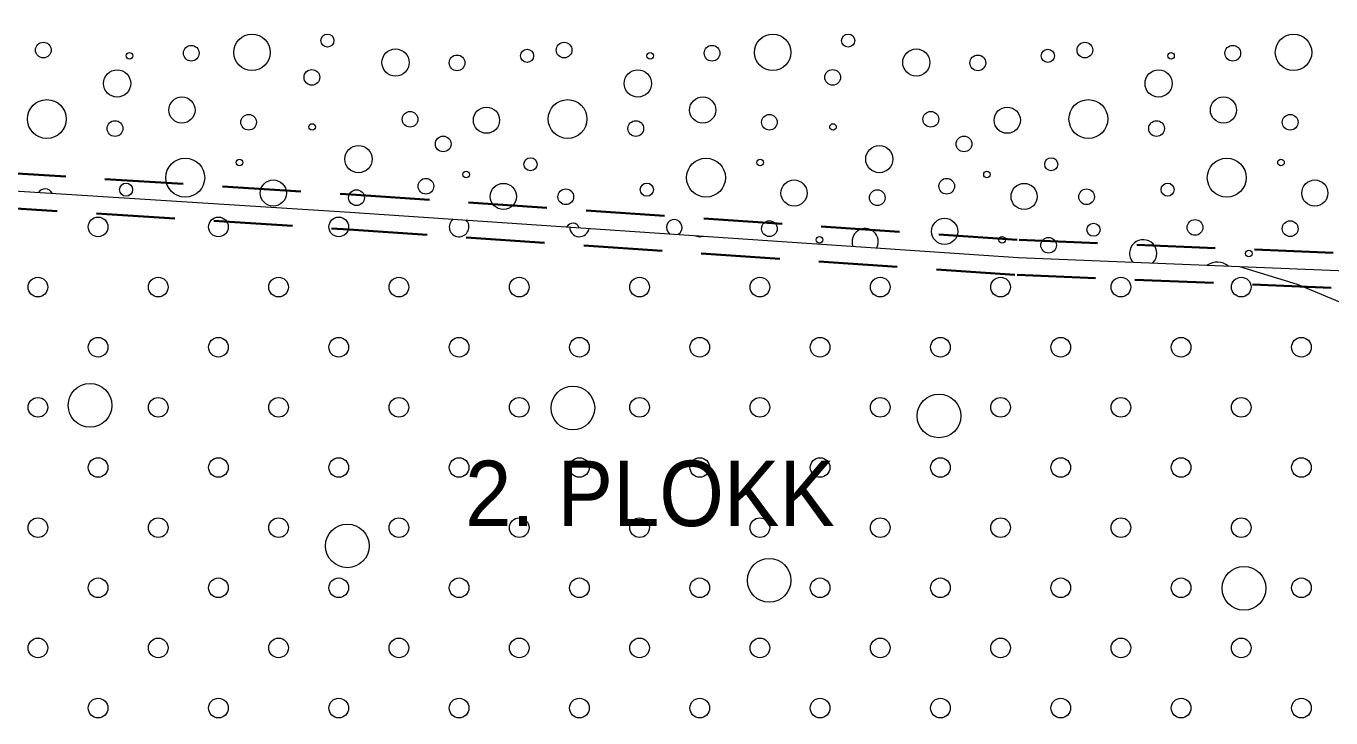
# Model space of a CAD drawing. Extents: x 640104 to 640970, y 6442278 to 6442689.
# Drawn here: x 640313.3 to 640373.1, y 6442364.5 to 6442396.3 of the extents above; entities that cross this region are included whole.
import ezdxf
from ezdxf.enums import TextEntityAlignment as Align

# ---------------------------------------------------------------- set-up
doc = ezdxf.new("R2010")
doc.units = 0
doc.header["$LTSCALE"] = 1.2
doc.linetypes.add('MEDIUM_DASHED', pattern=[4.5, 3, -1.5])
for name, color, linetype, lineweight in [('31', 7, 'Continuous', 13), ('35', 7, 'Continuous', 35), ('41', 7, 'Continuous', 13), ('42', 7, 'Continuous', 13), ('47', 7, 'Continuous', 13)]:
    doc.layers.add(name, color=color, linetype=linetype, lineweight=lineweight)

msp = doc.modelspace()

# ---------------------------------------------------------------- linework, layer by layer
at = {"layer": '31'}
for points in [[(640139.08, 6442423.82), (640151.96, 6442423.75), (640173.66, 6442421.26), (640213.16, 6442416.61), (640233.94, 6442414.53), (640242.79, 6442413.66), (640295.17, 6442389.83), (640328.15, 6442387.74), (640358.78, 6442385.66), (640377.96, 6442384.87), (640391.41, 6442383.72), (640397.31, 6442383.01), (640414.42, 6442381.45)], [(640368.92, 6442385.24), (640371.57, 6442384.43), (640374.23, 6442383.31), (640378.94, 6442380.49), (640385.79, 6442376.51), (640388.32, 6442375.25), (640390.29, 6442374.75), (640393.64, 6442373.85), (640400.93, 6442372.38), (640406.33, 6442371.82), (640411.39, 6442371.54), (640414.6, 6442371.41), (640423.41, 6442371.54), (640447.85, 6442370.88), (640460.41, 6442370.88), (640471.22, 6442370.34), (640473.77, 6442369.96)]]:
    msp.add_lwpolyline(points, dxfattribs=at)
at = {"layer": '35', "linetype": 'MEDIUM_DASHED'}
for points in [[(640153.52, 6442424.38), (640173.75, 6442422.06), (640213.24, 6442417.41), (640234.02, 6442415.33), (640243, 6442414.44), (640295.36, 6442390.62), (640328.2, 6442388.54), (640358.82, 6442386.46), (640378.01, 6442385.67), (640391.49, 6442384.52), (640397.4, 6442383.81), (640411.83, 6442382.49)], [(640153.52, 6442422.77), (640173.56, 6442420.47), (640213.07, 6442415.82), (640233.86, 6442413.74), (640242.58, 6442412.88), (640294.97, 6442389.04), (640328.09, 6442386.94), (640358.73, 6442384.86), (640377.91, 6442384.07), (640391.32, 6442382.92), (640397.23, 6442382.22), (640405.71, 6442381.44)]]:
    msp.add_lwpolyline(points, dxfattribs=at)
at = {"layer": '41'}
for centre, radius in [((640323.658, 6442395.062), 0.834), ((640327.116, 6442395.6), 0.3), ((640347.527, 6442395.062), 0.834), ((640350.985, 6442395.6), 0.3), ((640371.396, 6442395.062), 0.834), ((640314.095, 6442395.166), 0.36), ((640318.044, 6442394.901), 0.15), ((640320.875, 6442395.023), 0.36), ((640330.238, 6442394.594), 0.624), ((640336.266, 6442394.901), 0.3), ((640337.964, 6442395.166), 0.36), ((640341.913, 6442394.901), 0.15), ((640344.744, 6442395.023), 0.36), ((640354.107, 6442394.594), 0.624), ((640360.135, 6442394.901), 0.3), ((640361.833, 6442395.166), 0.36), ((640365.782, 6442394.901), 0.15), ((640368.613, 6442395.023), 0.36), ((640333.057, 6442394.579), 0.36), ((640356.926, 6442394.579), 0.36), ((640317.475, 6442393.637), 0.624), ((640326.403, 6442393.914), 0.36), ((640341.344, 6442393.637), 0.624), ((640350.272, 6442393.914), 0.36), ((640365.213, 6442393.637), 0.624), ((640314.255, 6442392.005), 0.889), ((640320.447, 6442392.417), 0.6), ((640338.124, 6442392.005), 0.889), ((640344.316, 6442392.417), 0.6), ((640361.993, 6442392.005), 0.889), ((640368.185, 6442392.417), 0.6), ((640323.504, 6442391.856), 0.36), ((640330.904, 6442391.993), 0.36), ((640334.406, 6442391.949), 0.6), ((640347.373, 6442391.856), 0.36), ((640354.773, 6442391.993), 0.36), ((640358.275, 6442391.949), 0.6), ((640371.242, 6442391.856), 0.36), ((640317.38, 6442391.569), 0.36), ((640326.42, 6442391.64), 0.15), ((640341.249, 6442391.569), 0.36), ((640350.289, 6442391.64), 0.15), ((640365.118, 6442391.569), 0.36), ((640328.542, 6442390.169), 0.624), ((640332.423, 6442390.861), 0.36), ((640352.411, 6442390.169), 0.624), ((640356.292, 6442390.861), 0.36), ((640320.598, 6442389.315), 0.893), ((640336.422, 6442389.93), 0.3), ((640344.467, 6442389.315), 0.893), ((640360.291, 6442389.93), 0.3), ((640368.336, 6442389.315), 0.893), ((640323.084, 6442390.008), 0.15), ((640333.476, 6442389.465), 0.15), ((640346.953, 6442390.008), 0.15), ((640357.345, 6442389.465), 0.15), ((640370.822, 6442390.008), 0.15), ((640317.888, 6442388.766), 0.3), ((640324.635, 6442388.61), 0.6), ((640331.631, 6442388.924), 0.36), ((640335.18, 6442388.454), 0.6), ((640341.757, 6442388.766), 0.3), ((640348.504, 6442388.61), 0.6), ((640355.5, 6442388.924), 0.36), ((640359.049, 6442388.454), 0.6), ((640365.626, 6442388.766), 0.3), ((640372.373, 6442388.61), 0.6), ((640328.449, 6442388.398), 0.36), ((640338.042, 6442388.44), 0.36), ((640352.318, 6442388.398), 0.36), ((640361.911, 6442388.44), 0.36), ((640347.373, 6442386.977), 0.36), ((640355.404, 6442386.854), 0.6), ((640362.229, 6442386.929), 0.3), ((640366.881, 6442387.034), 0.36), ((640371.242, 6442386.977), 0.36), ((640349.668, 6442386.464), 0.15), ((640358.041, 6442386.464), 0.15), ((640360.17, 6442386.217), 0.36), ((640369.349, 6442385.843), 0.15)]:
    msp.add_circle(centre, radius, dxfattribs=at)
for centre, radius, start, end in [((640314.173, 6442388.44), 0.36, 27.17527, 145.58427), ((640338.36, 6442386.929), 0.3, 19.35786, 152.87247), ((640343.012, 6442387.034), 0.36, 299.20248, 233.02785), ((640351.762, 6442386.386), 0.6, 331.71524, 200.51508), ((640364.505, 6442385.848), 0.624, 315.02616, 220.25663), ((640367.897, 6442384.605), 0.835, 52.08446, 123.19833)]:
    msp.add_arc(centre, radius, start, end, dxfattribs=at)
at = {"layer": '42'}
for centre in [(640316.604, 6442387.058), (640322.119, 6442387.058), (640327.635, 6442387.058), (640313.846, 6442384.3), (640319.362, 6442384.3), (640324.877, 6442384.3), (640330.392, 6442384.3), (640335.908, 6442384.3), (640341.423, 6442384.3), (640346.939, 6442384.3), (640352.454, 6442384.3), (640357.97, 6442384.3), (640363.485, 6442384.3), (640369, 6442384.3), (640316.604, 6442381.542), (640322.119, 6442381.542), (640327.635, 6442381.542), (640333.15, 6442381.542), (640338.666, 6442381.542), (640344.181, 6442381.542), (640349.696, 6442381.542), (640355.212, 6442381.542), (640360.727, 6442381.542), (640366.243, 6442381.542), (640371.758, 6442381.542), (640313.846, 6442378.785), (640319.362, 6442378.785), (640324.877, 6442378.785), (640330.392, 6442378.785), (640335.908, 6442378.785), (640341.423, 6442378.785), (640346.939, 6442378.785), (640352.454, 6442378.785), (640357.97, 6442378.785), (640363.485, 6442378.785), (640369, 6442378.785), (640316.604, 6442376.027), (640322.119, 6442376.027), (640327.635, 6442376.027), (640333.15, 6442376.027), (640338.666, 6442376.027), (640344.181, 6442376.027), (640349.696, 6442376.027), (640355.212, 6442376.027), (640360.727, 6442376.027), (640366.243, 6442376.027), (640371.758, 6442376.027), (640313.846, 6442373.269), (640319.362, 6442373.269), (640324.877, 6442373.269), (640330.392, 6442373.269), (640335.908, 6442373.269), (640341.423, 6442373.269), (640346.939, 6442373.269), (640352.454, 6442373.269), (640357.97, 6442373.269), (640363.485, 6442373.269), (640369, 6442373.269), (640316.604, 6442370.511), (640322.119, 6442370.511), (640327.635, 6442370.511), (640333.15, 6442370.511), (640338.666, 6442370.511), (640344.181, 6442370.511), (640349.696, 6442370.511), (640355.212, 6442370.511), (640360.727, 6442370.511), (640366.243, 6442370.511), (640371.758, 6442370.511), (640313.846, 6442367.754), (640319.362, 6442367.754), (640324.877, 6442367.754), (640330.392, 6442367.754), (640335.908, 6442367.754), (640341.423, 6442367.754), (640346.939, 6442367.754), (640352.454, 6442367.754), (640357.97, 6442367.754), (640363.485, 6442367.754), (640369, 6442367.754), (640316.604, 6442364.996), (640322.119, 6442364.996), (640327.635, 6442364.996), (640333.15, 6442364.996), (640338.666, 6442364.996), (640344.181, 6442364.996), (640349.696, 6442364.996), (640355.212, 6442364.996), (640360.727, 6442364.996), (640366.243, 6442364.996), (640371.758, 6442364.996)]:
    msp.add_circle(centre, 0.45, dxfattribs=at)
for centre, start, end in [((640333.15, 6442387.058), 126.57099, 45.65933), ((640338.666, 6442387.058), 180.09974, 352.13059), ((640344.181, 6442387.058), 240.25776, 291.97257)]:
    msp.add_arc(centre, 0.45, start, end, dxfattribs=at)
at = {"layer": '47'}
for centre in [(640316.236, 6442378.877), (640338.365, 6442378.756), (640355.145, 6442378.391), (640328.03, 6442372.433), (640347.363, 6442370.853), (640369.128, 6442370.488)]:
    msp.add_circle(centre, 1, dxfattribs=at)

# ---------------------------------------------------------------- texts
at = {"layer": '35', "width": 0.95}
msp.add_text('2. PLOKK', height=3, dxfattribs=at).set_placement((640341.9, 6442373.34), align=Align.CENTER)

doc.saveas('drawing.dxf')
